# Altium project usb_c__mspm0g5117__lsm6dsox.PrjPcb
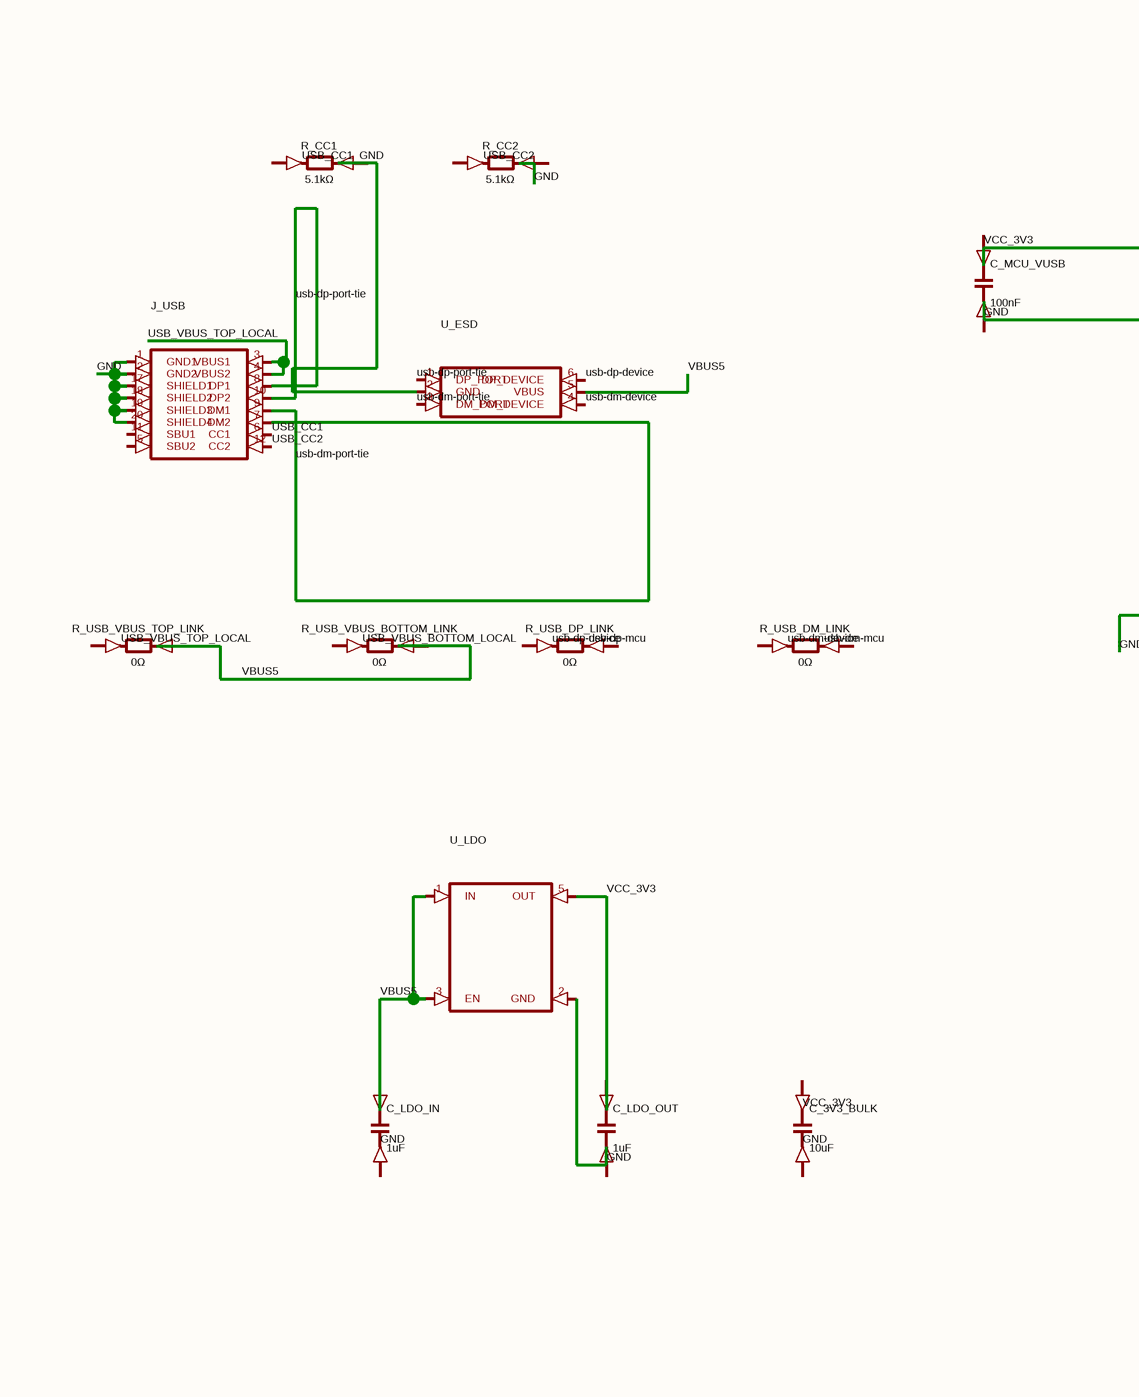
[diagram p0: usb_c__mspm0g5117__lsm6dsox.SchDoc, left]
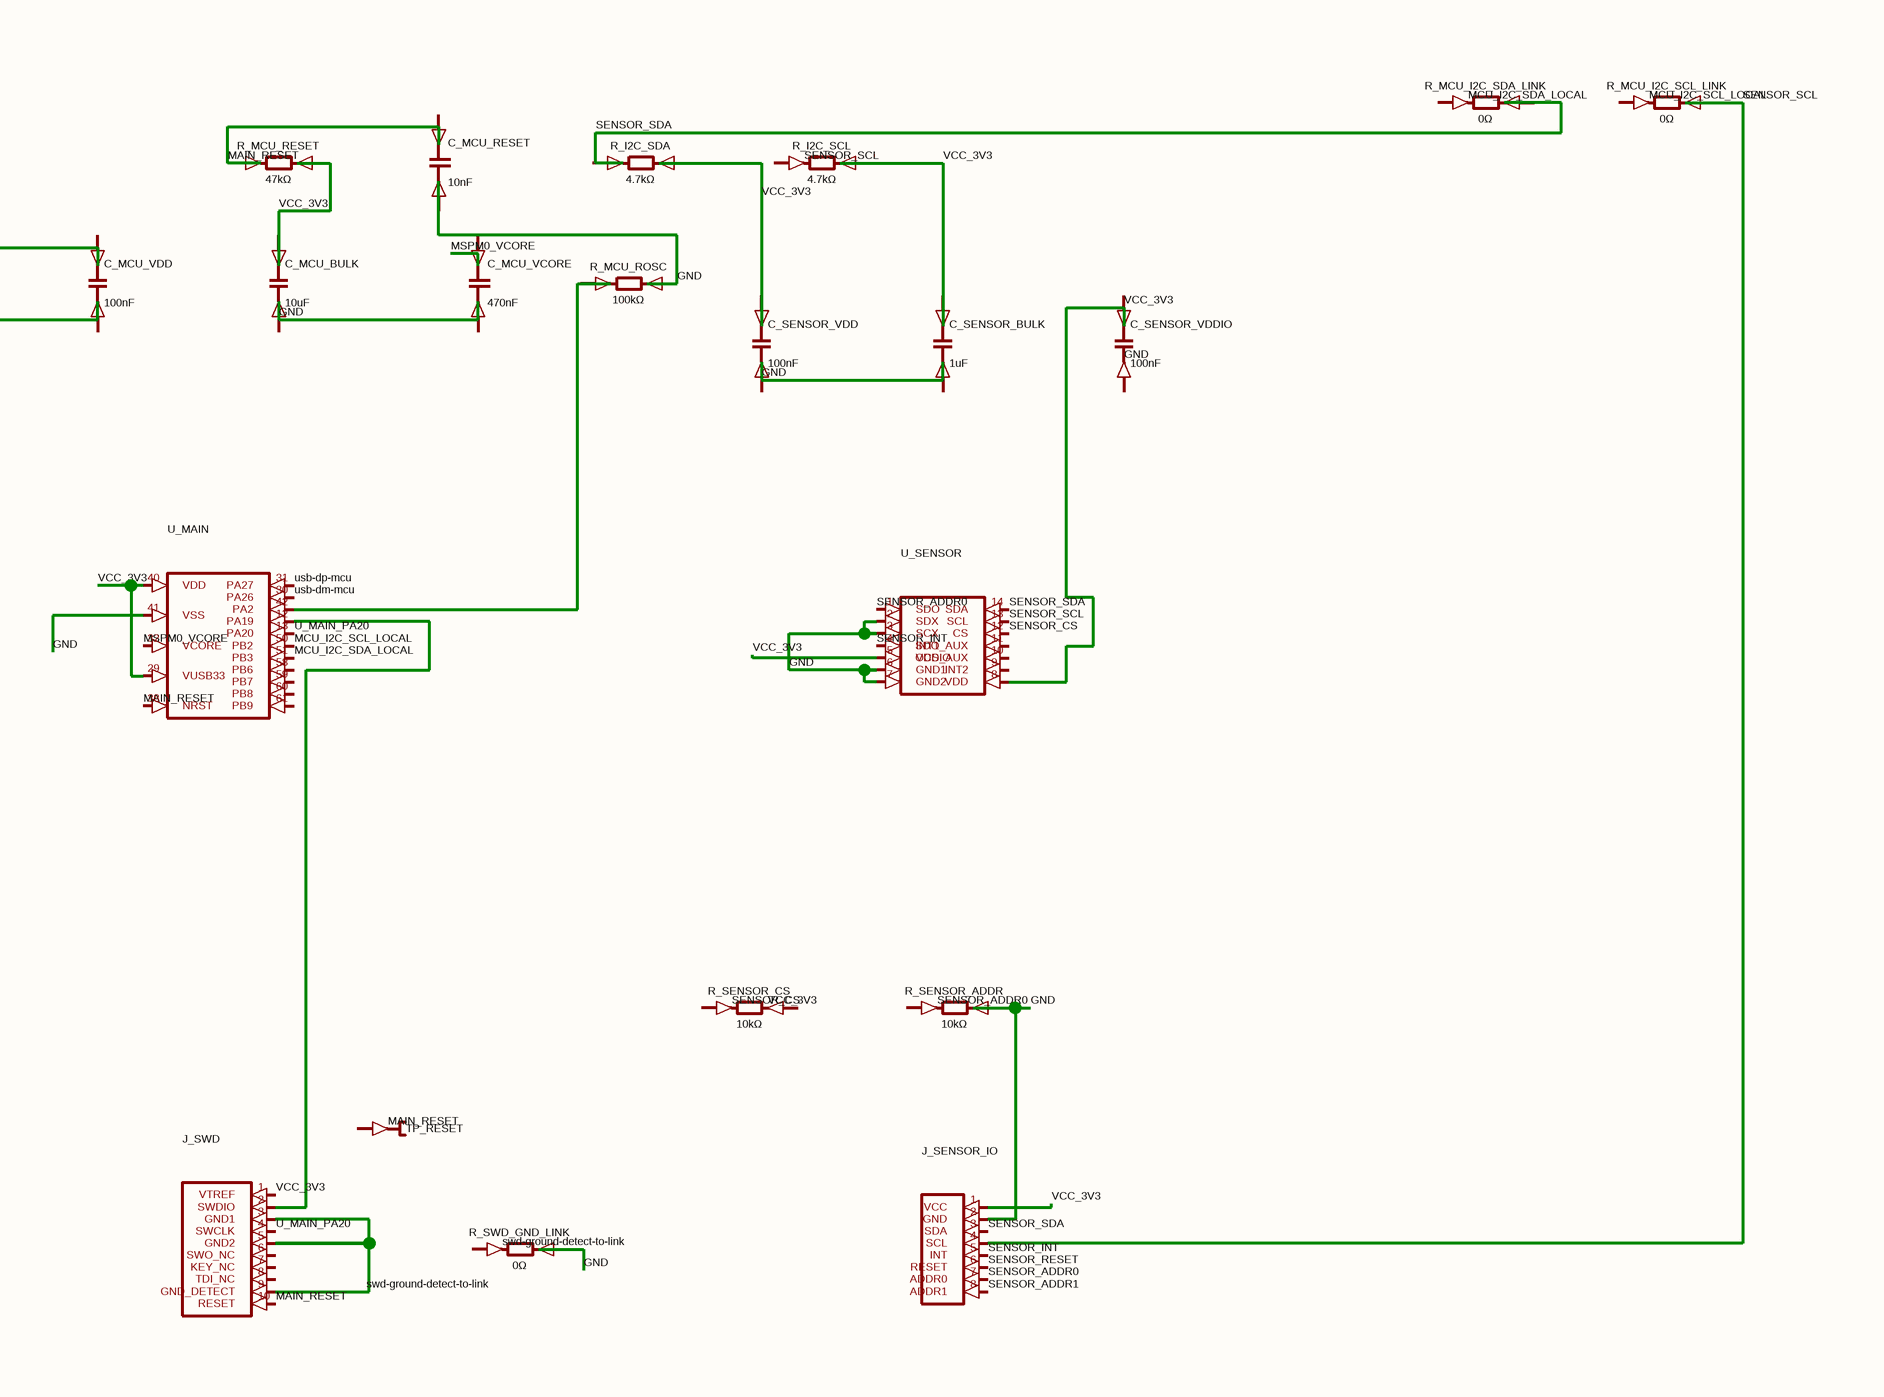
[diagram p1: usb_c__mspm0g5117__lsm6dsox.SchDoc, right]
1 sheet, 34 parts. Net scope: global (net labels, ports and power ports of the same name join across sheets).
Board file: usb_c__mspm0g5117__lsm6dsox.PcbDoc

## Sheet usb_c__mspm0g5117__lsm6dsox.SchDoc
size 286 x 151 mm

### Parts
C_3V3_BULK  10uF
C_LDO_IN  1uF
C_LDO_OUT  1uF
C_MCU_BULK  10uF
C_MCU_RESET  10nF
C_MCU_VCORE  470nF
C_MCU_VDD  100nF
C_MCU_VUSB  100nF
C_SENSOR_BULK  1uF
C_SENSOR_VDD  100nF
C_SENSOR_VDDIO  100nF
J_SENSOR_IO  (no value)
J_SWD  (no value)
J_USB  (no value)
R_CC1  5.1kΩ
R_CC2  5.1kΩ
R_I2C_SCL  4.7kΩ
R_I2C_SDA  4.7kΩ
R_MCU_I2C_SCL_LINK  0Ω
R_MCU_I2C_SDA_LINK  0Ω
R_MCU_RESET  47kΩ
R_MCU_ROSC  100kΩ
R_SENSOR_ADDR  10kΩ
R_SENSOR_CS  10kΩ
R_SWD_GND_LINK  0Ω
R_USB_DM_LINK  0Ω
R_USB_DP_LINK  0Ω
R_USB_VBUS_BOTTOM_LINK  0Ω
R_USB_VBUS_TOP_LINK  0Ω
TP_RESET  (no value)
U_ESD  (no value)
U_LDO  (no value)
U_MAIN  (no value)
U_SENSOR  (no value)

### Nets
GND: C_LDO_OUT.1(anode) C_MCU_BULK.1(anode) C_MCU_RESET.2(cathode) C_MCU_VCORE.1(anode) C_SENSOR_BULK.1(anode) C_SENSOR_VDD.1(anode) J_SENSOR_IO.1(VCC) J_SENSOR_IO.2(GND) J_SWD.1(VTREF) J_USB.1(GND1) J_USB.2(GND2) J_USB.8(DP1) J_USB.10(DP2) J_USB.17(SHIELD1) J_USB.18(SHIELD2) J_USB.19(SHIELD3) J_USB.20(SHIELD4) R_CC1.2(cathode) R_I2C_SCL.2(cathode) R_I2C_SDA.2(cathode) R_MCU_RESET.2(cathode) R_MCU_ROSC.2(cathode) R_SENSOR_ADDR.2(cathode) R_SWD_GND_LINK.2(cathode) U_ESD.1(DP_PORT) U_ESD.2(GND) U_LDO.2(GND) U_LDO.5(OUT) U_MAIN.29(VUSB33) U_MAIN.40(VDD) U_MAIN.41(VSS) U_SENSOR.2(SDX) U_SENSOR.3(SCX) U_SENSOR.5(VDDIO) U_SENSOR.6(GND1) U_SENSOR.7(GND2) U_SENSOR.8(VDD)  [also labelled usb-dp-port-tie, VCC_3V3]
MAIN_RESET: J_SWD.10(RESET) R_MCU_RESET.1(anode) U_MAIN.38(NRST)
MCU_I2C_SCL_LOCAL: U_MAIN.50(PB2)
MCU_I2C_SDA_LOCAL: U_MAIN.51(PB3)
MSPM0_VCORE: U_MAIN.32(VCORE)
SENSOR_ADDR0: J_SENSOR_IO.7(ADDR0) U_SENSOR.1(SDO)
SENSOR_ADDR1: J_SENSOR_IO.8(ADDR1)
SENSOR_CS: U_SENSOR.12(CS)
SENSOR_INT: J_SENSOR_IO.5(INT) U_SENSOR.4(INT1)
SENSOR_RESET: J_SENSOR_IO.6(RESET)
SENSOR_SCL: J_SENSOR_IO.4(SCL) R_MCU_I2C_SCL_LINK.2(cathode) U_SENSOR.13(SCL)
SENSOR_SDA: J_SENSOR_IO.3(SDA) R_MCU_I2C_SDA_LINK.2(cathode) U_SENSOR.14(SDA)
swd-ground-detect-to-link: J_SWD.3(GND1) J_SWD.5(GND2) J_SWD.9(GND_DETECT)
U_MAIN_PA20: J_SWD.4(SWCLK) U_MAIN.13(PA20)
usb-dm-device: U_ESD.4(DM_DEVICE)
usb-dm-mcu: U_MAIN.30(PA26)
usb-dm-port-tie: J_USB.7(DM2) J_USB.9(DM1) U_ESD.3(DM_PORT)
usb-dp-device: U_ESD.6(DP_DEVICE)
usb-dp-mcu: U_MAIN.31(PA27)
USB_CC1: J_USB.6(CC1)
USB_CC2: J_USB.12(CC2)
USB_VBUS_TOP_LOCAL: J_USB.3(VBUS1) J_USB.4(VBUS2)
VBUS5: C_LDO_IN.1(anode) R_USB_VBUS_BOTTOM_LINK.2(cathode) R_USB_VBUS_TOP_LINK.2(cathode) U_ESD.5(VBUS) U_LDO.1(IN) U_LDO.3(EN)
NetJ_SWD_2: J_SWD.2(SWDIO) U_MAIN.12(PA19)
NetR_MCU_ROSC_1: R_MCU_ROSC.1(anode) U_MAIN.42(PA2)

Not connected (* = marked no-connect by the designer): C_3V3_BULK 1(anode) 2(cathode); C_LDO_IN 2(cathode); C_LDO_OUT 2(cathode); C_MCU_BULK 2(cathode); C_MCU_RESET 1(anode); C_MCU_VCORE 2(cathode); C_MCU_VDD 1(anode) 2(cathode); C_MCU_VUSB 1(anode) 2(cathode); C_SENSOR_BULK 2(cathode); C_SENSOR_VDD 2(cathode); C_SENSOR_VDDIO 1(anode) 2(cathode); J_SWD 6(SWO_NC) 7(KEY_NC) 8(TDI_NC); J_USB 5(SBU2) 11(SBU1); R_CC1 1(anode); R_CC2 1(anode) 2(cathode); R_I2C_SCL 1(anode); R_I2C_SDA 1(anode); R_MCU_I2C_SCL_LINK 1(anode); R_MCU_I2C_SDA_LINK 1(anode); R_SENSOR_ADDR 1(anode); R_SENSOR_CS 1(anode) 2(cathode); R_SWD_GND_LINK 1(anode); R_USB_DM_LINK 1(anode) 2(cathode); R_USB_DP_LINK 1(anode) 2(cathode); R_USB_VBUS_BOTTOM_LINK 1(anode); R_USB_VBUS_TOP_LINK 1(anode); TP_RESET 1(pin1); U_MAIN 58(PB6) 59(PB7) 60(PB8) 61(PB9); U_SENSOR 9(INT2) 10(OCS_AUX) 11(SDO_AUX)

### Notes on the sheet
- Labels drawn without touching a wire or pin: GND, MAIN_RESET, MCU_I2C_SCL_LOCAL, MCU_I2C_SDA_LOCAL, SENSOR_ADDR0, SENSOR_CS, SENSOR_SCL, swd-ground-detect-to-link, usb-dm-device, usb-dm-mcu, usb-dp-device, usb-dp-mcu, USB_CC1, USB_CC2, USB_VBUS_BOTTOM_LOCAL, USB_VBUS_TOP_LOCAL, VCC_3V3

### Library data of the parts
C_3V3_BULK C_LDO_IN C_LDO_OUT C_MCU_BULK C_MCU_RESET C_MCU_VCORE C_MCU_VDD C_MCU_VUSB C_SENSOR_BULK C_SENSOR_VDD C_SENSOR_VDDIO = capacitor_down
J_SENSOR_IO = J_SENSOR_IO
J_SWD = J_SWD
J_USB = J_USB
R_CC1 R_CC2 R_I2C_SCL R_I2C_SDA R_MCU_I2C_SCL_LINK R_MCU_I2C_SDA_LINK R_MCU_RESET R_MCU_ROSC R_SENSOR_ADDR R_SENSOR_CS R_SWD_GND_LINK R_USB_DM_LINK R_USB_DP_LINK R_USB_VBUS_BOTTOM_LINK R_USB_VBUS_TOP_LINK = boxresistor_right
TP_RESET = testpoint_right
U_ESD = U_ESD
U_LDO = U_LDO
U_MAIN = U_MAIN
U_SENSOR = U_SENSOR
